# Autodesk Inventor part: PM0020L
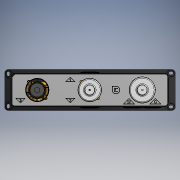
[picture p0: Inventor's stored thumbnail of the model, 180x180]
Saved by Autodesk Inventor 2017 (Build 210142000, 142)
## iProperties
Created: 2021-07
Part Number: PM0020L
Material: Generico
Document SubType Name: Modeling
Designer: CIANI
Density: 1 g/cm^3
Appearance: Default
Author: CIANI
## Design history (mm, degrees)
feature "Base3"
node "Solido1"
node "Solido4"
